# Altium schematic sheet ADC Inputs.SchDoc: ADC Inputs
size 431 x 279 mm; Date: Not shown in title block; ApprovedBy: Not shown in title block; CheckedBy: Not shown in title block; Author: Not shown in title block; CompanyName: Not shown in title block; Engineer: Not shown in title block; Organization: Not shown in title block; Address1: Not shown in title block; Address2: Not shown in title block; Address3: Not shown in title block; Address4: Not shown in title block; DocumentNumber: 1; Revision: Use project parameter SCH_Rev; SheetNumber: 9; SheetTotal: 15; PageSetup: Record=PageOptions¦CenterHorizontal=True¦CenterVertical=True¦PrintScale=1.00¦XCorrection=1.00¦YCorrection=1.00¦PrintKind=0¦BorderSize=5000000¦LeftOffset=0¦BottomOffset=0¦Orientation=2¦PaperLength=1000¦PaperWidth=1000¦Scale=100¦PaperSource=15¦PrintQuality=600¦MediaType=1¦DitherType=10¦PaperKind=Letter¦PrintScaleMode=1
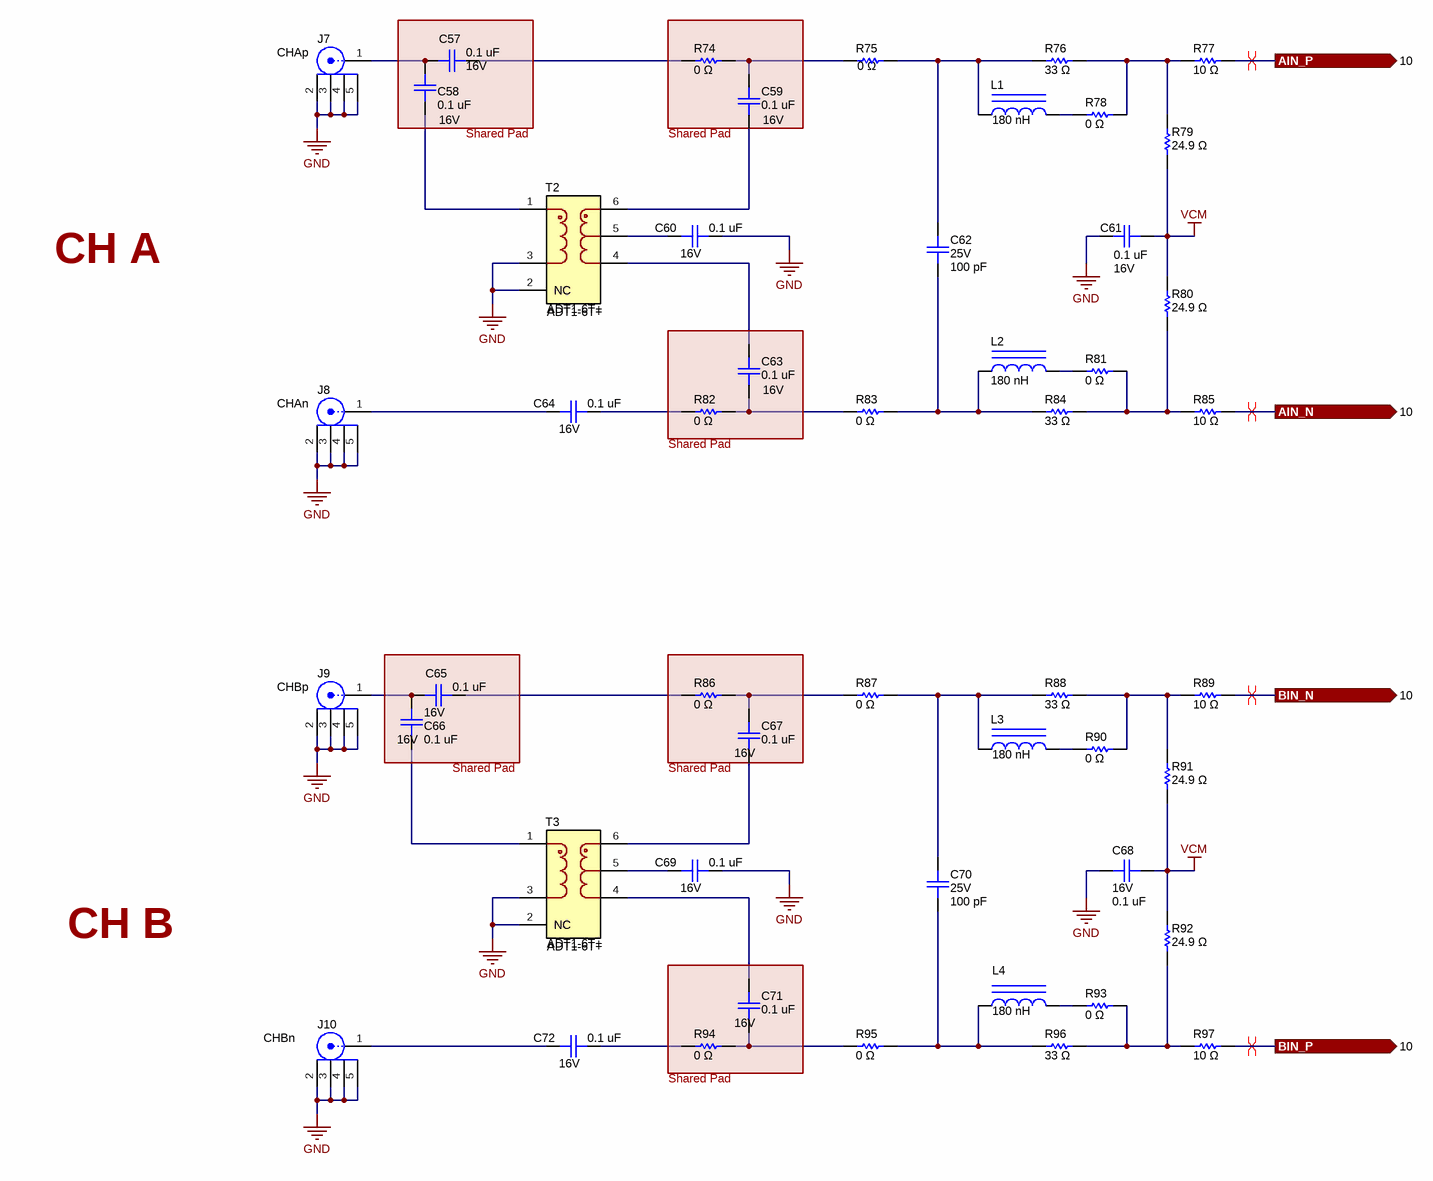
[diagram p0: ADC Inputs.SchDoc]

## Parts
(Parts that share a designator on the sheet are numbered #1, #2 ... from top to bottom, then left to right.)
?#1  Shared Pad  (graphical)
?#2  Shared Pad  (graphical)
?#3  Shared Pad  (graphical)
?#4  Shared Pad  (graphical)
?#5  Shared Pad  (graphical)
?#6  Shared Pad  (graphical)
C57  value 0.1 uF  Voltage - Rated: 16V  [0201_cap]  (hidden comment: GRM033Z71C104ME14D)
C58  value 0.1 uF  Voltage - Rated: 16V  [0201_cap]  (hidden comment: GRM033Z71C104ME14D)
C59  value 0.1 uF  Voltage - Rated: 16V  [0201_cap]  (hidden comment: GRM033Z71C104ME14D)
C60  value 0.1 uF  Voltage - Rated: 16V  [0201_cap]  (hidden comment: GRM033Z71C104ME14D)
C61  value 0.1 uF  Voltage - Rated: 16V  [0201_cap]  (hidden comment: GRM033Z71C104ME14D)
C62  value 100 pF  Voltage - Rated: 25V  [0201_cap]  (hidden comment: CGA1A2X7R1E101M030BA)
C63  value 0.1 uF  Voltage - Rated: 16V  [0201_cap]  (hidden comment: GRM033Z71C104ME14D)
C64  value 0.1 uF  Voltage - Rated: 16V  [0201_cap]  (hidden comment: GRM033Z71C104ME14D)
C65  value 0.1 uF  Voltage - Rated: 16V  [0201_cap]  (hidden comment: GRM033Z71C104ME14D)
C66  value 0.1 uF  Voltage - Rated: 16V  [0201_cap]  (hidden comment: GRM033Z71C104ME14D)
C67  value 0.1 uF  Voltage - Rated: 16V  [0201_cap]  (hidden comment: GRM033Z71C104ME14D)
C68  value 0.1 uF  Voltage - Rated: 16V  [0201_cap]  (hidden comment: GRM033Z71C104ME14D)
C69  value 0.1 uF  Voltage - Rated: 16V  [0201_cap]  (hidden comment: GRM033Z71C104ME14D)
C70  value 100 pF  Voltage - Rated: 25V  [0201_cap]  (hidden comment: CGA1A2X7R1E101M030BA)
C71  value 0.1 uF  Voltage - Rated: 16V  [0201_cap]  (hidden comment: GRM033Z71C104ME14D)
C72  value 0.1 uF  Voltage - Rated: 16V  [0201_cap]  (hidden comment: GRM033Z71C104ME14D)
J7  Text1: CHAp  [FP-132134-15_CONN_SMA_JACK-MFG]  (hidden comment: 132134-15)
J8  Text1: CHAn  [FP-132134-15_CONN_SMA_JACK-MFG]  (hidden comment: 132134-15)
J9  Text1: CHBp  [FP-132134-15_CONN_SMA_JACK-MFG]  (hidden comment: 132134-15)
J10  Text1: CHBn  [FP-132134-15_CONN_SMA_JACK-MFG]  (hidden comment: 132134-15)
L1  180 nH  [IND_LQG15H]
L2  180 nH  [IND_LQG15H]
L3  180 nH  [IND_LQG15H]
L4  180 nH  [IND_LQG15H]
R74  value 0 Ω  [0201]  (hidden comment: ERJ-1GN0R00C)
R75  value 0 Ω  [0201]  (hidden comment: ERJ-1GN0R00C)
R76  value 33 Ω  [0201]  (hidden comment: ERJ-1GNF33R0C)
R77  value 10 Ω  [0201]  (hidden comment: ERJ-1GNF10R0C)
R78  value 0 Ω  [0201]  (hidden comment: ERJ-1GN0R00C)
R79  value 24.9 Ω  [0201]  (hidden comment: ERJ-1GNF24R9C)
R80  value 24.9 Ω  [0201]  (hidden comment: ERJ-1GNF24R9C)
R81  value 0 Ω  [0201]  (hidden comment: ERJ-1GN0R00C)
R82  value 0 Ω  [0201]  (hidden comment: ERJ-1GN0R00C)
R83  value 0 Ω  [0201]  (hidden comment: ERJ-1GN0R00C)
R84  value 33 Ω  [0201]  (hidden comment: ERJ-1GNF33R0C)
R85  value 10 Ω  [0201]  (hidden comment: ERJ-1GNF10R0C)
R86  value 0 Ω  [0201]  (hidden comment: ERJ-1GN0R00C)
R87  value 0 Ω  [0201]  (hidden comment: ERJ-1GN0R00C)
R88  value 33 Ω  [0201]  (hidden comment: ERJ-1GNF33R0C)
R89  value 10 Ω  [0201]  (hidden comment: ERJ-1GNF10R0C)
R90  value 0 Ω  [0201]  (hidden comment: ERJ-1GN0R00C)
R91  value 24.9 Ω  [0201]  (hidden comment: ERJ-1GNF24R9C)
R92  value 24.9 Ω  [0201]  (hidden comment: ERJ-1GNF24R9C)
R93  value 0 Ω  [0201]  (hidden comment: ERJ-1GN0R00C)
R94  value 0 Ω  [0201]  (hidden comment: ERJ-1GN0R00C)
R95  value 0 Ω  [0201]  (hidden comment: ERJ-1GN0R00C)
R96  value 33 Ω  [0201]  (hidden comment: ERJ-1GNF33R0C)
R97  value 10 Ω  [0201]  (hidden comment: ERJ-1GNF10R0C)
T2  ADT1-6T+  [CD637]
T3  ADT1-6T+  [CD637]

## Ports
AIN_N (out, see 10), AIN_P (out, see 10), BIN_N (out, see 10), BIN_P (out, see 10)

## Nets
GND: C60.2 C61.1 C68.1 C69.2 J7.2 J7.3 J7.4 J7.5 J8.2 J8.3 J8.4 J8.5 J9.2 J9.3 J9.4 J9.5 J10.2 J10.3 J10.4 J10.5 T2.2(NC) T2.3 T3.2(NC) T3.3
VCM: C61.2 C68.2 R79.1 R80.2 R91.1 R92.2
AIN_N: R85.2 ; port AIN_N
AIN_P: R77.2 ; port AIN_P
BIN_N: R89.2 ; port BIN_N
BIN_P: R97.2 ; port BIN_P
NetC57_1: C57.1 C58.1 J7.1
NetC57_2: C57.2 R74.1
NetC58_2: C58.2 T2.1
NetC59_1: C59.1 T2.6
NetC59_2: C59.2 R74.2 R75.1
NetC60_1: C60.1 T2.5
NetC62_1: C62.1 L2.1 R83.2 R84.1
NetC62_2: C62.2 L1.1 R75.2 R76.1
NetC63_1: C63.1 R82.2 R83.1
NetC63_2: C63.2 T2.4
NetC64_1: C64.1 J8.1
NetC64_2: C64.2 R82.1
NetC65_1: C65.1 C66.1 J9.1
NetC65_2: C65.2 R86.1
NetC66_2: C66.2 T3.1
NetC67_1: C67.1 T3.6
NetC67_2: C67.2 R86.2 R87.1
NetC69_1: C69.1 T3.5
NetC70_1: C70.1 L4.1 R95.2 R96.1
NetC70_2: C70.2 L3.1 R87.2 R88.1
NetC71_1: C71.1 R94.2 R95.1
NetC71_2: C71.2 T3.4
NetC72_1: C72.1 J10.1
NetC72_2: C72.2 R94.1
NetL1_2: L1.2 R78.1
NetL2_2: L2.2 R81.1
NetL3_2: L3.2 R90.1
NetL4_2: L4.2 R93.1
NetR76_2: R76.2 R77.1 R78.2 R79.2
NetR80_1: R80.1 R81.2 R84.2 R85.1
NetR88_2: R88.2 R89.1 R90.2 R91.2
NetR92_1: R92.1 R93.2 R96.2 R97.1

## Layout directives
differential pair: AIN_N, AIN_P, BIN_N, BIN_P

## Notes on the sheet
- CH A
- CH B

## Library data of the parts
?#1-?#6 = Swizzle: Schematic notation to show that the pads of two components should be overlapped
C57-C61 C63-C69 C71 C72 = capcc09270: CAP CER 0.1UF 16V X7R 0201; Manufacturer: Murata Electronics; CompType: Capacitor Ceramic; Tolerance: ±20%; SizeX_mm: 0.6; SizeY_mm: 0.3; SizeZ_mm: 0.33
C62 C70 = capcc06388: CAP CER 100PF 25V X7R 0201; Manufacturer: TDK Corporation; CompType: Capacitor Ceramic; Tolerance: ±20%; SizeX_mm: 0.6; SizeY_mm: 0.3; SizeZ_mm: 0.33
J7-J10 = 132134-15: SMA Connector Jack, Female Socket 50Ohm Surface Mount, Through Hole Solder; Manufacturer: Amphenol RF; UniqueID: cmp00028; CompType: RF Connector
L1-L4 = LQG15HSR18J02D: Inductor, Multilayer, Air Core, 180 nH, 0.14 A, 3.38 ohm, SMD; Manufacturer: MuRata; Isat: 0.14A @ % inductance drop; Irms: 0.14A @ C rise; Green_Lifecycle: Active; SizeAreaWB_mm2: 3; DCR_ohm: 3.38; Green_REACh: Passed; Value: 180nH; Imax_A: 140mA; SizeZ_mm: 0.55; SizeX_mm: 1; SizeY_mm: 0.5; Value2: 0.14A; AEC Category: Q200
R74 R75 R78 R81-R83 R86 R87 R90 R93-R95 = RSMD020101699: RES SMD 0 OHM JUMPER 1/20W 0201; Manufacturer: Panasonic Electronic Components; CompType: Resistor SMD; Power (Watts): 0.05W, 1/20W
R76 R84 R88 R96 = RSMD020100013: RES SMD 33 OHM 1% 1/20W 0201; Manufacturer: Panasonic Electronic Components; CompType: Resistor SMD; Power (Watts): 0.05W, 1/20W; Temperature Coefficient: ±200ppm/°C
R77 R85 R89 R97 = RSMD020100179: RES SMD 10 OHM 1% 1/20W 0201; Manufacturer: Panasonic Electronic Components; CompType: Resistor SMD; Power (Watts): 0.05W, 1/20W; Temperature Coefficient: ±200ppm/°C
R79 R80 R91 R92 = RSMD020100010: RES SMD 24.9 OHM 1% 1/20W 0201; Manufacturer: Panasonic Electronic Components; CompType: Resistor SMD; Power (Watts): 0.05W, 1/20W; Temperature Coefficient: ±200ppm/°C
T2 T3 = ADT1-6T+: Transformer 50Ω/0.03 to 125 MHz; Manufacturer: Mini-Circuits; Rsec1_ohm: 50; Symbol Name: SYM-ADT1-6T+; Ns1toNp: 1:1; SizeZ_mm: .206inch; AEC Qualified: No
